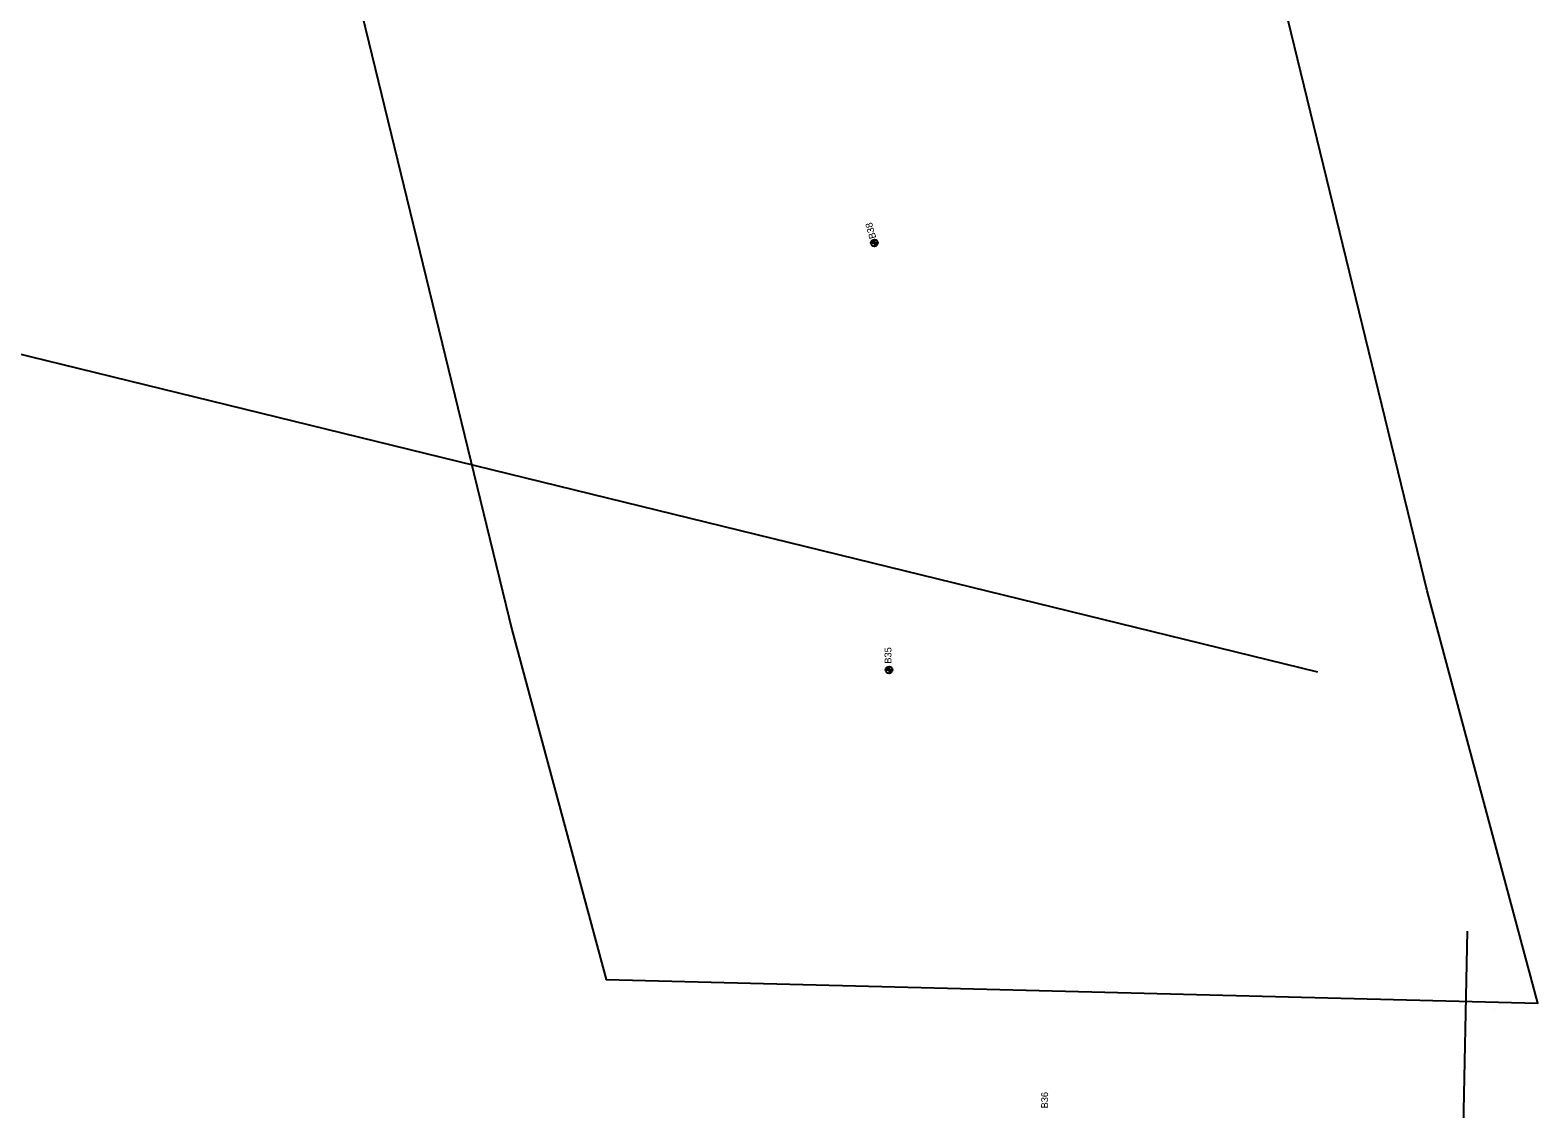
# Model space of a CAD drawing. Extents: x 311409 to 379449, y 121539 to 224848.
# Drawn here: x 359951 to 362127, y 147995 to 149551 of the extents above; entities that cross this region are included whole.
import ezdxf

# ---------------------------------------------------------------- set-up
doc = ezdxf.new("R2010")
doc.units = 0
for name, color, linetype in [('CA-TEXT', 7, 'Continuous'), ('E_SOIL_BORE2 [KAPUR_CADDS_LEVELS]', 7, 'Continuous'), ('P_MARK', 7, 'Continuous'), ('P_TC', 7, 'Continuous'), ('SIGNS-POLES', 7, 'Continuous')]:
    doc.layers.add(name, color=color, linetype=linetype)

msp = doc.modelspace()

# ---------------------------------------------------------------- linework, layer by layer
at = {"layer": 'CA-TEXT'}
msp.add_line((354592.7, 150393.1), (361809.2, 148625.3), dxfattribs=at)
at = {"layer": 'P_MARK'}
for p, q in [((361164.4, 149244.4), (361174.4, 149244.4)), ((361169.4, 149249.4), (361169.4, 149239.4)), ((361190.6, 148633.1), (361190.6, 148623.1)), ((361185.6, 148628.1), (361195.6, 148628.1))]:
    msp.add_line(p, q, dxfattribs=at)
for centre in [(361169.4, 149244.4), (361190.6, 148628.1)]:
    msp.add_circle(centre, 5, dxfattribs=at)
for centre, radius, start, end in [((361169.4, 149244.4), 4.5, 89.9869, 179.9869), ((361169.4, 149244.4), 4, 89.9869, 179.9869), ((361169.4, 149244.4), 3.5, 89.9869, 179.9869), ((361169.4, 149244.4), 3, 89.9869, 179.9869), ((361169.4, 149244.4), 2.5, 89.9869, 179.9869), ((361169.4, 149244.4), 2, 89.9869, 179.9869), ((361169.4, 149244.4), 1.5, 89.9869, 179.9869), ((361169.4, 149244.4), 1, 89.9869, 179.9869), ((361169.4, 149244.4), 0.5, 89.9869, 179.9869), ((361169.4, 149244.4), 4.5, 269.9869, 359.9869), ((361169.4, 149244.4), 4, 269.9869, 359.9869), ((361169.4, 149244.4), 3.5, 269.9869, 359.9869), ((361169.4, 149244.4), 3, 269.9869, 359.9869), ((361169.4, 149244.4), 2.5, 269.9869, 359.9869), ((361169.4, 149244.4), 2, 269.9869, 359.9869), ((361169.4, 149244.4), 1.5, 269.9869, 359.9869), ((361169.4, 149244.4), 1, 269.9869, 359.9869), ((361169.4, 149244.4), 0.5, 269.9869, 359.9869), ((361190.6, 148628.1), 4.5, 89.9869, 179.9869), ((361190.6, 148628.1), 4, 89.9869, 179.9869), ((361190.6, 148628.1), 3.5, 89.9869, 179.9869), ((361190.6, 148628.1), 3, 89.9869, 179.9869), ((361190.6, 148628.1), 2.5, 89.9869, 179.9869), ((361190.6, 148628.1), 2, 89.9869, 179.9869), ((361190.6, 148628.1), 1.5, 89.9869, 179.9869), ((361190.6, 148628.1), 1, 89.9869, 179.9869), ((361190.6, 148628.1), 0.5, 89.9869, 179.9869), ((361190.6, 148628.1), 4.5, 269.9869, 359.9869), ((361190.6, 148628.1), 4, 269.9869, 359.9869), ((361190.6, 148628.1), 3.5, 269.9869, 359.9869), ((361190.6, 148628.1), 3, 269.9869, 359.9869), ((361190.6, 148628.1), 2.5, 269.9869, 359.9869), ((361190.6, 148628.1), 2, 269.9869, 359.9869), ((361190.6, 148628.1), 1.5, 269.9869, 359.9869), ((361190.6, 148628.1), 1, 269.9869, 359.9869), ((361190.6, 148628.1), 0.5, 269.9869, 359.9869)]:
    msp.add_arc(centre, radius, start, end, dxfattribs=at)
at = {"layer": 'P_TC'}
msp.add_line((362064.8, 148138.5), (362064.8, 148138.5), dxfattribs=at)
msp.add_lwpolyline([(359969.9, 151461.4), (360646.7, 148684.4), (360782.1, 148181.1), (362127.2, 148146.9), (361967.2, 148742.4), (361289.2, 151524)], dxfattribs=at)
at = {"layer": 'SIGNS-POLES'}
msp.add_line((362017.3, 147846.2), (362025.5, 148251.1), dxfattribs=at)

# ---------------------------------------------------------------- texts
at = {"layer": 'E_SOIL_BORE2 [KAPUR_CADDS_LEVELS]'}
for s, rotation, p in [('B38', 105.7466, (361172.2, 149251.8)), ('B35', 89.9869, (361194.1, 148637)), ('B36', 89.9869, (361420.2, 147995.1))]:
    msp.add_text(s, height=10, rotation=rotation, dxfattribs=at).set_placement(p)

doc.saveas('drawing.dxf')
